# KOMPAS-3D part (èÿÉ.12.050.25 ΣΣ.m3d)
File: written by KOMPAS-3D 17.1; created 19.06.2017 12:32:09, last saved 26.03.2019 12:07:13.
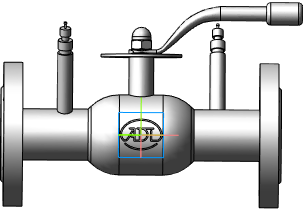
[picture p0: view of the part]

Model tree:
1. Операция без истории:2  (labels: Сталь 20  ГОСТ 1050-88)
